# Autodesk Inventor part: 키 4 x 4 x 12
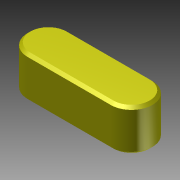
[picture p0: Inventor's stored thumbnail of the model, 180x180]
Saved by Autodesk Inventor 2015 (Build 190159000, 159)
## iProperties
Created: 2025-08
Part Number: 키 4 x 4 x 12
Material: 일반
Document SubType Name: Modeling
Designer: USER
Density: 1 g/cm^3
Appearance: 기본값
Author: USER
Author: jhkim
Description: 키 및 해당 키홈
Creation Date: 2025-08-05
Sending System: Autodesk Inventor 2026
Preprocessor: ST-DEVELOPER v20.1
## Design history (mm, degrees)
node "키 4 x 4 x 121"
body "Solid1"
node "기준1"
